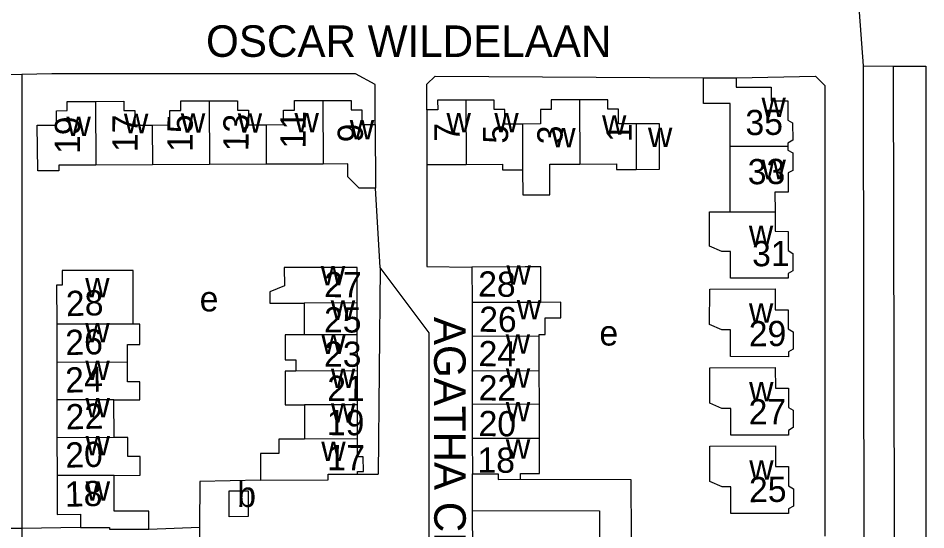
# Model space of a CAD drawing. Extents: x 159441 to 162086, y 388175 to 389787.
# Drawn here: x 160888 to 161031.9, y 388547.5 to 388628.7 of the extents above; entities that cross this region are included whole.
import ezdxf

# ---------------------------------------------------------------- set-up
doc = ezdxf.new("R2010")
doc.units = 0
for name, color, linetype in [('BLT_Basislijn', 7, 'Continuous'), ('BLT_Bebouwing', 7, 'Continuous'), ('BLT_Centroide', 7, 'Continuous'), ('BLT_Huisnummer', 7, 'Continuous'), ('BLT_Huisnummer_ tussenligend', 7, 'Continuous'), ('BLT_Onderverdeling_panden', 7, 'Continuous'), ('BLT_Straatnaam', 7, 'Continuous'), ('BLT_Vlakafsluiter', 7, 'Continuous')]:
    doc.layers.add(name, color=color, linetype=linetype)

msp = doc.modelspace()

# ---------------------------------------------------------------- linework, layer by layer
at = {"layer": 'BLT_Basislijn'}
for p, q in [((160893.38, 388619.88), (160888.59, 388619.8)), ((160888.59, 388619.8), (160888.59, 388547.74)), ((160945.4, 388589.14), (160945.1, 388556.32)), ((160941.84, 388556.34), (160945.1, 388556.32)), ((160953.17, 388537.93), (160953.17, 388556.27)), ((160960.06, 388550.56), (160960.04, 388556.41)), ((160916.84, 388555.2), (160916.75, 388547.94)), ((160926.44, 388555.4), (160916.84, 388555.2)), ((160960.11, 388541.09), (160960.06, 388550.56)), ((160888.59, 388547.74), (160886.08, 388547.71)), ((160897.91, 388547.87), (160888.59, 388547.74)), ((160888.59, 388547.74), (160888.59, 388509.14)), ((160908.74, 388547.62), (160916.75, 388547.94)), ((160916.75, 388547.94), (160916.64, 388537.88))]:
    msp.add_line(p, q, dxfattribs=at)
for points in [[(161022.26, 388463.04), (161022.08, 388621.14)], [(161022.08, 388621.14), (161026.77, 388621.12)], [(161026.77, 388621.12), (161031.94, 388621.11)], [(161026.77, 388621.12), (161027.02, 388500), (161027.15, 388463.04)], [(161031.94, 388621.11), (161031.88, 388463.04), (161027.15, 388463.04)], [(160888.59, 388619.8), (160881.27, 388619.68), (160870.84, 388614.61)], [(160944.64, 388611.85), (160944.64, 388618.22), (160941.52, 388619.88), (160893.38, 388619.88)], [(160952.82, 388614.17), (160952.81, 388618.27), (160954.15, 388619.51)], [(160954.15, 388619.51), (160996.67, 388619.28)], [(161001.88, 388619.27), (161014.43, 388619.51), (161015.91, 388618.03), (161015.91, 388546.48)], [(160952.83, 388605.48), (160952.81, 388589.3), (160959.98, 388589.21)], [(160945.4, 388589.14), (160944.67, 388601.75)], [(160953.17, 388556.27), (160953.17, 388578.77), (160945.4, 388589.14)], [(160967.67, 388555.53), (160985.17, 388555.48), (160985.2, 388546.31)], [(160960.06, 388550.56), (160980.18, 388550.5), (160980.22, 388541.17), (160960.11, 388541.09)]]:
    msp.add_lwpolyline(points, dxfattribs=at)
at = {"layer": 'BLT_Bebouwing'}
for p, q in [((160996.67, 388619.28), (161001.88, 388619.27)), ((160952.8, 388614.17), (160952.83, 388605.48)), ((160952.82, 388614.17), (160952.8, 388614.17)), ((160944.64, 388611.85), (160944.67, 388601.75)), ((161000.93, 388598), (161000.93, 388608.33)), ((160909.32, 388605.44), (160900.34, 388605.4)), ((160918.36, 388605.49), (160909.32, 388605.44)), ((160927.37, 388605.53), (160918.36, 388605.49)), ((160936.36, 388605.57), (160927.37, 388605.53)), ((160952.83, 388605.48), (160959.06, 388605.5)), ((161008.01, 388601.1), (161008.03, 388598)), ((160959.98, 388589.21), (160959.99, 388583.59)), ((160894.12, 388586.34), (160894.13, 388580.14)), ((160941.8, 388578.48), (160941.79, 388583.53)), ((160959.99, 388583.59), (160960, 388578.21)), ((160894.13, 388580.14), (160894.15, 388574.13)), ((160941.81, 388572.74), (160941.8, 388578.48)), ((160960, 388578.21), (160960.01, 388572.71)), ((160894.15, 388574.13), (160894.16, 388568.13)), ((160941.82, 388567.35), (160941.81, 388572.74)), ((160960.01, 388572.71), (160960.02, 388567.42)), ((160970.66, 388567.43), (160970.65, 388572.73)), ((160894.16, 388568.13), (160894.18, 388562.13)), ((160903.22, 388562.15), (160903.21, 388568.15)), ((160933.4, 388567.33), (160933.42, 388561.92)), ((160941.83, 388561.94), (160941.82, 388567.35)), ((160960.02, 388567.42), (160960.03, 388562.02)), ((160970.67, 388562.03), (160970.66, 388567.43)), ((160894.18, 388562.13), (160894.19, 388556.13))]:
    msp.add_line(p, q, dxfattribs=at)
for points in [[(161000.93, 388608.33), (161000.89, 388615.19), (160996.68, 388615.18), (160996.67, 388619.28)], [(161001.88, 388619.27), (161001.88, 388617.75), (161007.42, 388617.76), (161007.43, 388615.61), (161010.07, 388615.6), (161010.07, 388612.56), (161010.82, 388612.13), (161010.83, 388609.38), (161010.08, 388608.9), (161010.08, 388608.34)], [(160900.34, 388605.4), (160894.45, 388605.41), (160894.45, 388604.51), (160891.12, 388604.49), (160891.03, 388611.72), (160894.1, 388611.74), (160894.09, 388614.04), (160895.81, 388614.05), (160895.81, 388615.5), (160900.3, 388615.52)], [(160900.3, 388615.52), (160904.79, 388615.54), (160904.79, 388614.07), (160906.5, 388614.08), (160906.51, 388611.75), (160909.29, 388611.76)], [(160909.29, 388611.76), (160912.06, 388611.78), (160912.05, 388614.08), (160913.83, 388614.09), (160913.82, 388615.59), (160918.31, 388615.61)], [(160918.31, 388615.61), (160922.8, 388615.63), (160922.81, 388614.1), (160924.54, 388614.1), (160924.55, 388611.8), (160927.34, 388611.82)], [(160927.34, 388611.82), (160930.12, 388611.83), (160930.11, 388614.13), (160931.83, 388614.14), (160931.82, 388615.64), (160936.32, 388615.66)], [(160936.32, 388615.66), (160940.81, 388615.68), (160940.82, 388614.17), (160942.51, 388614.18), (160942.52, 388611.84), (160944.64, 388611.85)], [(160959.02, 388615.7), (160954.53, 388615.69), (160954.54, 388614.18), (160952.82, 388614.17)], [(160968.01, 388611.92), (160965.2, 388611.91), (160965.19, 388614.21), (160963.52, 388614.21), (160963.51, 388615.72), (160959.02, 388615.7)], [(160977.02, 388615.76), (160972.54, 388615.74), (160972.54, 388614.23), (160970.82, 388614.22), (160970.82, 388611.93), (160968.01, 388611.92)], [(160986, 388611.95), (160983.2, 388611.94), (160983.2, 388614.27), (160981.52, 388614.26), (160981.52, 388615.77), (160977.02, 388615.76)], [(160986.02, 388604.72), (160989.69, 388604.74), (160989.69, 388611.97), (160986, 388611.95)], [(161010.08, 388608.34), (161010.08, 388607.78), (161010.83, 388607.35), (161010.84, 388604.55), (161010.09, 388604.16), (161010.1, 388601.12), (161008.01, 388601.1)], [(160944.67, 388601.75), (160942.07, 388601.74), (160940.32, 388603.54), (160940.31, 388605.59), (160936.36, 388605.57)], [(160959.06, 388605.5), (160964.84, 388605.53), (160964.84, 388604.63), (160967.97, 388604.65)], [(160967.97, 388604.65), (160968.05, 388600.68), (160972.31, 388600.7), (160972.3, 388605.55), (160977.06, 388605.56)], [(160977.06, 388605.56), (160982.88, 388605.61), (160982.88, 388604.71), (160986.02, 388604.72)], [(160997.65, 388592.55), (160997.62, 388597.99), (161000.93, 388598)], [(161008.03, 388598), (161008.06, 388594.89), (161010.11, 388594.88), (161010.12, 388591.84), (161010.87, 388591.38), (161010.87, 388588.63), (161010.13, 388588.2), (161010.13, 388587.44), (161000.97, 388587.44), (161000.97, 388591.67), (160999.57, 388591.67), (160997.65, 388592.55)], [(160906.28, 388580.17), (160906.25, 388588.69), (160894.98, 388588.65), (160894.99, 388586.34), (160894.12, 388586.34)], [(160930.22, 388589.13), (160930.23, 388586.26), (160927.93, 388585.3), (160927.94, 388583.5), (160933.37, 388583.51)], [(160941.79, 388583.53), (160941.77, 388589.15), (160930.22, 388589.13)], [(160970.92, 388583.61), (160970.91, 388589.23), (160968.41, 388589.23), (160959.98, 388589.21)], [(160997.66, 388580.11), (160997.67, 388585.7), (161008.04, 388585.76), (161008.07, 388582.45), (161010.13, 388582.44), (161010.13, 388579.4), (161010.88, 388578.94), (161010.89, 388576.19), (161010.14, 388575.76), (161010.14, 388574.99), (161000.98, 388575), (161000.98, 388579.23), (160999.58, 388579.23), (160997.66, 388580.11)], [(160971.58, 388578.53), (160971.58, 388581.17), (160974.08, 388581.18), (160974.07, 388583.62), (160970.92, 388583.61)], [(160933.37, 388583.51), (160933.38, 388578.47)], [(160905.36, 388574.15), (160905.36, 388576.95), (160907.32, 388576.95), (160907.31, 388580.17), (160906.28, 388580.17)], [(160933.38, 388578.47), (160930.34, 388578.46), (160930.35, 388574.48), (160932.06, 388574.48), (160932.07, 388572.72)], [(160970.64, 388578.53), (160971.58, 388578.53)], [(160970.64, 388578.25), (160970.64, 388578.53)], [(160970.65, 388572.73), (160970.64, 388578.24)], [(160903.21, 388568.15), (160907.34, 388568.16), (160907.33, 388571.02), (160905.37, 388571.02), (160905.36, 388574.15)], [(160932.07, 388572.72), (160930.35, 388572.72), (160930.37, 388567.33), (160933.4, 388567.33)], [(160997.69, 388567.64), (160997.69, 388573.24), (161008.07, 388573.29), (161008.1, 388569.99), (161010.15, 388569.97), (161010.16, 388566.93), (161010.91, 388566.48), (161010.91, 388563.73), (161010.17, 388563.29), (161010.17, 388562.53), (161001.01, 388562.54), (161001.01, 388566.77), (160999.61, 388566.77), (160997.69, 388567.64)], [(160903.23, 388556.15), (160907.37, 388556.16), (160907.36, 388559.15), (160905.4, 388559.14), (160905.39, 388562.15), (160903.22, 388562.15)], [(160941.84, 388556.34), (160941.85, 388556.78), (160942.76, 388556.79), (160942.72, 388559.09), (160941.84, 388559.09), (160941.83, 388561.94)], [(160960.03, 388562.02), (160960.04, 388556.41)], [(160967.67, 388555.53), (160967.65, 388556.43), (160970.68, 388556.44), (160970.67, 388562.03)], [(160933.42, 388561.92), (160929.37, 388561.92), (160929.37, 388559.61), (160926.43, 388559.6), (160926.44, 388555.4)], [(160997.71, 388555.2), (160997.71, 388560.8), (161008.09, 388560.86), (161008.11, 388557.55), (161010.17, 388557.54), (161010.18, 388554.5), (161010.93, 388554.04), (161010.93, 388551.29), (161010.18, 388550.86), (161010.18, 388550.09), (161001.02, 388550.1), (161001.03, 388554.33), (160999.63, 388554.33), (160997.71, 388555.2)], [(160926.44, 388555.4), (160937.15, 388555.43), (160937.15, 388556.33), (160941.84, 388556.34)], [(160960.04, 388556.41), (160964.12, 388556.42), (160964.14, 388555.52), (160967.67, 388555.53)], [(160894.19, 388556.13), (160894.21, 388549.96), (160897.9, 388549.97), (160897.91, 388547.87)], [(160908.74, 388547.62), (160908.73, 388550.49), (160903.25, 388550.47), (160903.23, 388556.15)], [(160897.91, 388547.87), (160902.52, 388547.88), (160902.52, 388547.6), (160908.74, 388547.62)]]:
    msp.add_lwpolyline(points, dxfattribs=at)
msp.add_lwpolyline([(160921.48, 388553.7), (160924.47, 388553.71), (160924.49, 388549.61), (160921.5, 388549.59)], close=True, dxfattribs=at)
at = {"layer": 'BLT_Onderverdeling_panden'}
for p, q in [((160900.3, 388615.52), (160900.34, 388605.4)), ((160918.31, 388615.61), (160918.36, 388605.49)), ((160936.32, 388615.66), (160936.36, 388605.57)), ((160959.02, 388615.7), (160959.06, 388605.5)), ((160977.02, 388615.76), (160977.06, 388605.56)), ((160909.29, 388611.76), (160909.32, 388605.44)), ((160927.34, 388611.82), (160927.37, 388605.53)), ((160968.01, 388611.92), (160967.97, 388604.65)), ((160986, 388611.95), (160986.02, 388604.72)), ((161010.08, 388608.34), (161000.93, 388608.33)), ((161000.93, 388598), (161008.03, 388598)), ((160941.79, 388583.53), (160933.37, 388583.51)), ((160970.92, 388583.61), (160959.99, 388583.59)), ((160906.28, 388580.17), (160894.13, 388580.14)), ((160941.8, 388578.48), (160933.38, 388578.47)), ((160894.15, 388574.13), (160905.36, 388574.15)), ((160941.81, 388572.74), (160932.07, 388572.72)), ((160970.65, 388572.73), (160960.01, 388572.71)), ((160903.21, 388568.15), (160894.16, 388568.13)), ((160941.82, 388567.35), (160933.4, 388567.33)), ((160970.66, 388567.43), (160960.02, 388567.42)), ((160903.22, 388562.15), (160894.18, 388562.13)), ((160941.83, 388561.94), (160933.42, 388561.92)), ((160970.67, 388562.03), (160960.03, 388562.02)), ((160903.23, 388556.15), (160894.19, 388556.13))]:
    msp.add_line(p, q, dxfattribs=at)
msp.add_lwpolyline([(160970.64, 388578.24), (160960, 388578.21)], dxfattribs=at)
at = {"layer": 'BLT_Vlakafsluiter'}
msp.add_line((161022.08, 388621.14), (161021.4, 388629.68), dxfattribs=at)

# ---------------------------------------------------------------- texts
at = {"layer": 'BLT_Centroide'}
for s, p in [('w', (161005.88, 388613.06)), ('w', (160895.68, 388610)), ('w', (160904.8, 388610.47)), ('w', (160913.82, 388610.53)), ('w', (160922.84, 388610.56)), ('w', (160931.84, 388610.59)), ('w', (160940.61, 388609.47)), ('w', (160955.94, 388610.59)), ('w', (160963.52, 388610.62)), ('w', (160980.6, 388610.25)), ('w', (160972.54, 388608.22)), ('w', (160987.88, 388608.28)), ('w', (161005.88, 388603.17)), ('w', (161003.88, 388592.72)), ('w', (160936.01, 388586.31)), ('w', (160965.45, 388586.41)), ('w', (160898.65, 388584.41)), ('e', (160916.8, 388582.18)), ('w', (160937.59, 388580.84)), ('w', (160967.09, 388580.91)), ('w', (161003.89, 388580.38)), ('w', (160898.66, 388577.25)), ('e', (160980.18, 388576.76)), ('w', (160936.09, 388575.44)), ('w', (160965.32, 388575.47)), ('w', (160898.68, 388571.28)), ('w', (160937.61, 388570.03)), ('w', (160965.34, 388570.06)), ('w', (161003.92, 388567.91)), ('w', (160898.7, 388565.34)), ('w', (160965.34, 388564.72)), ('w', (160937.62, 388564.5)), ('w', (160898.71, 388559.34)), ('w', (160936.08, 388558.44)), ('w', (160965.35, 388558.78)), ('w', (161003.94, 388555.47)), ('w', (160898.73, 388552.12)), ('b', (160922.76, 388551.14))]:
    msp.add_text(s, height=4, dxfattribs=at).set_placement(p)
at = {"layer": 'BLT_Huisnummer'}
for s, rotation, p in [('35', 0.6141, (161003.35, 388610.15)), ('19', 89.7394, (160897.82, 388607.17)), ('13', 89.7394, (160924.54, 388607.59)), ('9', 89.7394, (160942.68, 388609.01)), ('7', 89.7394, (160958.01, 388609.09)), ('1', 89.7394, (160985.29, 388609.05)), ('31', 0.6034, (161004.41, 388589.33)), ('27', 359.6742, (160936.52, 388584.45)), ('28', 359.4052, (160960.94, 388584.55)), ('28', 1.6621, (160895.65, 388581.41)), ('29', 0.6034, (161003.89, 388576.63)), ('21', 359.6742, (160937.02, 388567.97)), ('22', 359.4052, (160961.01, 388568.06)), ('27', 0.6034, (161003.87, 388564.23)), ('22', 1.6621, (160895.62, 388563.43)), ('17', 359.6742, (160937.03, 388556.98)), ('18', 359.6742, (160960.84, 388556.59)), ('18', 1.6621, (160895.47, 388551.15)), ('25', 0.6034, (161003.92, 388551.89))]:
    msp.add_text(s, height=4, rotation=rotation, dxfattribs=at).set_placement(p)
at = {"layer": 'BLT_Huisnummer_ tussenligend'}
for s, rotation, p in [('17', 89.7394, (160906.95, 388607.47)), ('15', 89.7394, (160915.68, 388607.49)), ('11', 89.7394, (160933.59, 388608.03)), ('5', 89.7394, (160965.7, 388608.8)), ('3', 89.7394, (160974.33, 388608.7)), ('33', 0.6034, (161003.72, 388602.35)), ('25', 359.6742, (160936.5, 388578.85)), ('26', 359.4052, (160961.1, 388578.95)), ('26', 1.6621, (160895.56, 388575.23)), ('23', 359.6742, (160936.51, 388573.41)), ('24', 359.4052, (160961, 388573.5)), ('24', 1.6621, (160895.54, 388569.27)), ('19', 359.6742, (160936.96, 388562.54)), ('20', 359.4052, (160961, 388562.4)), ('20', 1.6621, (160895.56, 388557.36))]:
    msp.add_text(s, height=4, rotation=rotation, dxfattribs=at).set_placement(p)
at = {"layer": 'BLT_Straatnaam'}
for s, rotation, p in [('OSCAR WILDELAAN', 359.9724, (160917.81, 388622.59)), ('AGATHA CHRISTIELAAN', 270.0584, (160953.96, 388581.31))]:
    msp.add_text(s, height=5, rotation=rotation, dxfattribs=at).set_placement(p)

doc.saveas('drawing.dxf')
